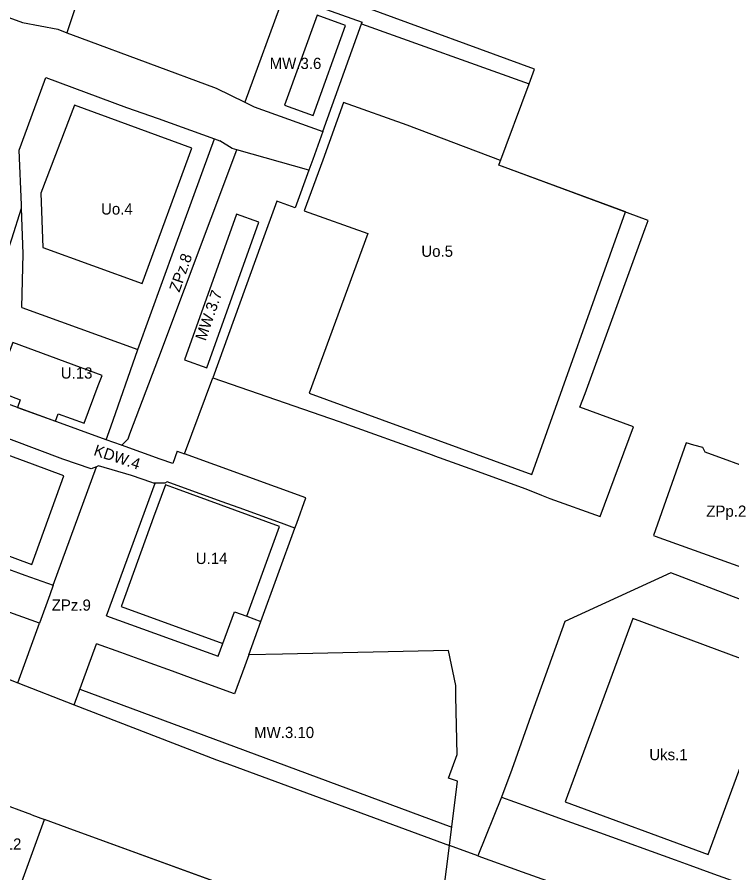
# Model space of a CAD drawing. Extents: x 7428239 to 7429836, y 5549133 to 5550853.
# Drawn here: x 7428694.2 to 7429012.7, y 5549884.9 to 5550266.4 of the extents above; entities that cross this region are included whole.
import ezdxf

# ---------------------------------------------------------------- set-up
doc = ezdxf.new("R2010")
doc.units = 0
for name, color, linetype in [('LIN_linie rozgraniczające', 7, 'Continuous'), ('LIN_nieprzekraczalna linia zabudowy', 7, 'Continuous'), ('TXT_Oznaczenia Przeznaczenia', 7, 'Continuous')]:
    doc.layers.add(name, color=color, linetype=linetype)

msp = doc.modelspace()

# ---------------------------------------------------------------- linework, layer by layer
at = {"layer": 'LIN_linie rozgraniczające'}
for p, q in [((7428813.18, 5550276.63), (7428795.72, 5550228.45)), ((7428924.77, 5550243.28), (7428850, 5550270.61)), ((7428696.63, 5550264.05), (7428712.27, 5550261)), ((7428847.7, 5550263.36), (7428922.3, 5550236.65)), ((7428922.3, 5550236.65), (7428924.77, 5550243.28)), ((7428908.84, 5550200.47), (7428922.3, 5550236.65)), ((7428830.38, 5550215.39), (7428825.9, 5550202.98)), ((7428779.91, 5550206.05), (7428782.13, 5550212.17)), ((7428764.5, 5550163.71), (7428779.91, 5550206.05)), ((7428825.9, 5550202.98), (7428824.16, 5550198.17)), ((7428824.16, 5550198.17), (7428818.13, 5550181.44)), ((7428975.37, 5550175.75), (7428908.84, 5550200.47)), ((7428809.85, 5550184.33), (7428802.95, 5550165.27)), ((7428818.13, 5550181.44), (7428809.85, 5550184.33)), ((7428974.09, 5550172.21), (7428975.37, 5550175.75)), ((7428947.38, 5550098.57), (7428974.09, 5550172.21)), ((7428747.94, 5550118.19), (7428764.5, 5550163.71)), ((7428802.95, 5550165.27), (7428781.46, 5550105.66)), ((7428696.26, 5550136.99), (7428747.94, 5550118.19)), ((7428735.94, 5550083.72), (7428747.94, 5550118.19)), ((7428768.83, 5550071.75), (7428781.46, 5550105.66)), ((7428781.46, 5550105.66), (7428837.66, 5550086.17)), ((7428944.97, 5550092.56), (7428947.38, 5550098.57)), ((7428968.89, 5550083.71), (7428944.97, 5550092.56)), ((7428733.88, 5550078.05), (7428735.94, 5550083.72)), ((7428837.66, 5550086.17), (7428879.07, 5550071.27)), ((7428954.04, 5550043.82), (7428968.89, 5550083.71)), ((7428740.76, 5550075.55), (7428733.88, 5550078.05)), ((7428765.45, 5550072.99), (7428768.83, 5550071.75)), ((7428822.87, 5550052.1), (7428768.83, 5550071.75)), ((7428879.07, 5550071.27), (7428880.14, 5550070.89)), ((7428880.14, 5550070.89), (7428895.99, 5550065.13)), ((7428710.28, 5550013.16), (7428729.5, 5550066.01)), ((7428895.99, 5550065.13), (7428920.89, 5550056.1)), ((7428734.08, 5549999.48), (7428755.65, 5550058.66)), ((7428920.89, 5550056.1), (7428927.88, 5550053.34)), ((7428927.88, 5550053.34), (7428931.57, 5550051.88)), ((7428818.77, 5550040.81), (7428822.87, 5550052.1)), ((7428931.57, 5550051.88), (7428954.04, 5550043.82)), ((7428802.85, 5549997.03), (7428817.99, 5550038.66)), ((7428817.99, 5550038.66), (7428818.76, 5550040.79)), ((7428818.76, 5550040.79), (7428818.77, 5550040.81)), ((7428694.78, 5550018.71), (7428697.6, 5550017.68)), ((7428985.48, 5550018.65), (7428938.31, 5549997.03)), ((7428697.6, 5550017.68), (7428710.28, 5550013.16)), ((7428710.28, 5550013.16), (7428708.72, 5550008.86)), ((7428708.72, 5550008.86), (7428704.16, 5549996.32)), ((7428734.08, 5549999.48), (7428783.77, 5549981.52)), ((7428788.92, 5549995.61), (7428791.01, 5550001.34)), ((7428791.01, 5550001.34), (7428796.51, 5549999.34)), ((7428796.51, 5549999.34), (7428802.85, 5549997.03)), ((7428694.46, 5549969.64), (7428704.16, 5549996.32)), ((7428785.83, 5549987.13), (7428788.92, 5549995.61)), ((7428797.45, 5549982.18), (7428802.85, 5549997.03)), ((7428719.65, 5549959.9), (7428729.56, 5549987.08)), ((7428740.34, 5549983.16), (7428729.56, 5549987.08)), ((7428783.77, 5549981.52), (7428785.83, 5549987.13)), ((7428886.38, 5549984.07), (7428812.44, 5549982.5)), ((7428889.67, 5549968.43), (7428886.38, 5549984.07)), ((7428753.5, 5549978.38), (7428740.34, 5549983.16)), ((7428797.45, 5549982.18), (7428795.65, 5549977.23)), ((7428812.44, 5549982.5), (7428797.45, 5549982.18)), ((7428763.37, 5549974.79), (7428753.5, 5549978.38)), ((7428795.65, 5549977.23), (7428791.09, 5549964.7)), ((7428680.32, 5549975.11), (7428694.46, 5549969.64)), ((7428772.67, 5549971.4), (7428763.37, 5549974.79)), ((7428694.46, 5549969.64), (7428719.65, 5549959.9)), ((7428791.09, 5549964.7), (7428772.67, 5549971.4)), ((7428889.76, 5549963.63), (7428889.67, 5549968.43)), ((7428890.24, 5549937.66), (7428889.76, 5549963.63)), ((7428719.65, 5549959.9), (7428783.02, 5549935.39)), ((7428783.02, 5549935.39), (7428789.31, 5549933.09)), ((7428886.47, 5549927.23), (7428890.24, 5549937.66)), ((7428789.31, 5549933.09), (7428886.9, 5549897.16)), ((7428890.47, 5549925.78), (7428886.47, 5549927.23)), ((7428886.9, 5549897.16), (7428890.47, 5549925.78)), ((7428700.73, 5549910.8), (7428681.94, 5549917.67)), ((7428909.98, 5549918.74), (7428899.56, 5549892.48)), ((7428909.98, 5549918.74), (7428921.55, 5549914.56)), ((7428921.55, 5549914.56), (7428937.07, 5549908.95)), ((7428694.29, 5549875.52), (7428706.34, 5549908.74)), ((7428700.73, 5549910.8), (7428706.34, 5549908.74)), ((7428716.51, 5549905.02), (7428706.34, 5549908.74)), ((7428937.07, 5549908.95), (7428953.72, 5549902.94)), ((7428861.9, 5549852.15), (7428716.51, 5549905.02)), ((7428953.72, 5549902.94), (7428987.39, 5549890.78)), ((7428880.21, 5549845.49), (7428886.9, 5549897.16)), ((7428899.56, 5549892.48), (7428886.9, 5549897.16)), ((7428899.56, 5549892.48), (7428919.18, 5549885.41)), ((7428987.39, 5549890.78), (7428993.96, 5549888.41)), ((7428919.18, 5549885.41), (7428930.47, 5549881.33)), ((7428993.96, 5549888.41), (7429002.91, 5549885.17)), ((7429002.91, 5549885.17), (7429018.14, 5549879.67))]:
    msp.add_line(p, q, dxfattribs=at)
for points in [[(7428774.34, 5550317.09), (7428726, 5550316.32), (7428726.24, 5550301.32), (7428726.42, 5550290.09), (7428716.31, 5550259.45)], [(7428665.17, 5550274.78), (7428671.25, 5550273.2), (7428696.63, 5550264.05)], [(7428813.18, 5550276.63), (7428847.92, 5550264.11)], [(7428830.38, 5550215.39), (7428847.7, 5550263.36), (7428847.92, 5550264.11)], [(7428712.27, 5550261), (7428716.31, 5550259.45), (7428721.92, 5550257.29), (7428782.94, 5550234.74), (7428795.72, 5550228.45), (7428799.81, 5550226.43), (7428830.38, 5550215.39)], [(7428696.15, 5550181.23), (7428696.09, 5550182.78), (7428695.16, 5550207.09), (7428704.73, 5550233.4), (7428706.97, 5550239.46), (7428742.92, 5550226.17), (7428757.08, 5550221.19), (7428782.13, 5550212.17), (7428784.54, 5550211.3)], [(7428824.16, 5550198.17), (7428792.12, 5550207.28), (7428790.09, 5550207.86), (7428784.54, 5550211.3)], [(7428740.76, 5550075.55), (7428741.04, 5550075.68), (7428743.67, 5550078.42), (7428744.49, 5550080.6), (7428757.32, 5550114.73), (7428792.12, 5550207.28)], [(7428682.3, 5550142.05), (7428689.53, 5550160.66), (7428691.77, 5550167.64), (7428696.15, 5550181.23)], [(7428696.26, 5550136.99), (7428696.93, 5550160.97), (7428696.15, 5550181.23)], [(7428733.88, 5550078.05), (7428694.3, 5550092.41), (7428683.29, 5550096.41)], [(7428761.01, 5550059.22), (7428759.96, 5550058.64), (7428755.65, 5550058.66), (7428754.95, 5550058.66), (7428754.25, 5550058.97), (7428745.09, 5550062.01), (7428730.44, 5550066.4), (7428729.5, 5550066.01), (7428727.12, 5550065.03), (7428714.51, 5550069.34), (7428691.75, 5550077.92), (7428686.8, 5550079.72), (7428687.28, 5550081.07), (7428686.76, 5550081.22), (7428686.13, 5550083.11), (7428685.63, 5550084.53), (7428684.79, 5550085.6), (7428679.8, 5550087.58)], [(7429032.54, 5550061.79), (7429024.72, 5550064.82), (7429024.38, 5550063.89), (7429000.78, 5550072.42), (7428999.81, 5550074.51), (7428995.7, 5550075.64), (7428992.26, 5550076.61), (7428977.71, 5550035.34), (7428978.55, 5550035.04), (7429017.02, 5550021.18)], [(7428765.45, 5550072.99), (7428763.57, 5550067.47), (7428757.91, 5550069.33), (7428740.76, 5550075.55)], [(7428817.99, 5550038.66), (7428812.05, 5550040.82), (7428793.17, 5550047.62), (7428785.15, 5550050.45), (7428761.01, 5550059.22)], [(7428628.82, 5550054.34), (7428631.27, 5550046.51), (7428633.22, 5550044.37), (7428656.8, 5550035.59), (7428668.69, 5550028.81), (7428681.6, 5550023.4), (7428694.78, 5550018.71)], [(7428704.16, 5549996.32), (7428670.08, 5550008.51), (7428633.54, 5550021.58)], [(7429025.73, 5550003.32), (7429016.5, 5550006.84), (7428985.48, 5550018.65)], [(7428938.31, 5549997.03), (7428928.29, 5549969.34), (7428923.81, 5549956.97)], [(7428923.81, 5549956.97), (7428914.57, 5549931.03), (7428909.98, 5549918.74)]]:
    msp.add_lwpolyline(points, dxfattribs=at)
at = {"layer": 'LIN_nieprzekraczalna linia zabudowy'}
for points in [[(7428840.5, 5550262.62), (7428827.86, 5550267.22), (7428813.4, 5550227.15), (7428826.08, 5550222.62), (7428840.5, 5550262.62)], [(7428923.52, 5550062.53), (7428965.31, 5550179.69), (7428908.84, 5550200.47), (7428909.61, 5550202.54), (7428867.95, 5550218.24), (7428839.65, 5550228.34), (7428830.4, 5550202.6), (7428822.14, 5550180.01), (7428850.42, 5550169.92), (7428824.34, 5550098.74), (7428923.52, 5550062.53)], [(7428772.11, 5550208.05), (7428719.74, 5550227.15), (7428704.74, 5550187.88), (7428705.71, 5550163.74)], [(7428705.71, 5550163.74), (7428749.93, 5550147.61), (7428772.11, 5550208.05)], [(7428768.84, 5550113.59), (7428778.66, 5550110.15), (7428801.91, 5550175.05), (7428792.01, 5550178.54), (7428768.84, 5550113.59)], [(7428730.33, 5550102.14), (7428732.09, 5550106.68), (7428692.23, 5550121.39), (7428690.6, 5550117.05), (7428684.24, 5550100.1), (7428695.57, 5550095.81), (7428694.3, 5550092.41), (7428711.24, 5550086.26), (7428712.45, 5550089.61), (7428724.1, 5550085.39), (7428730.33, 5550102.14)], [(7428715.06, 5550061.91), (7428701.07, 5550067.07), (7428671.04, 5550078.17), (7428666.19, 5550073.87), (7428645.67, 5550054.64), (7428641.86, 5550044.19), (7428700.72, 5550022.48), (7428715.06, 5550061.91)], [(7428796.51, 5549999.34), (7428811.1, 5550039.33), (7428765.19, 5550056.14), (7428760.24, 5550057.95), (7428755.02, 5550043.56), (7428740.65, 5550003.97), (7428740.53, 5550003.64), (7428785.83, 5549987.13)], [(7429032.2, 5549974.74), (7428968.53, 5549998.27), (7428938.39, 5549916.68), (7429002.06, 5549893.16), (7429032.2, 5549974.74)], [(7428722.16, 5549966.78), (7428887.91, 5549905.25)], [(7428861.9, 5549852.15), (7428716.51, 5549905.02), (7428706.34, 5549908.74)]]:
    msp.add_lwpolyline(points, dxfattribs=at)

# ---------------------------------------------------------------- texts
at = {"layer": 'TXT_Oznaczenia Przeznaczenia'}
for s, p in [('MW.3.6', (7428806.72, 5550243.31)), ('Uo.4', (7428731.58, 5550178.4)), ('Uo.5', (7428874.31, 5550159.57)), ('U.13', (7428713.65, 5550105.27)), ('ZPp.2', (7429001.28, 5550043.69)), ('U.14', (7428773.79, 5550022.62)), ('ZPz.9', (7428709.6, 5550001.82)), ('MW.3.10', (7428799.79, 5549945.04)), ('Uks.1', (7428975.89, 5549935.16)), ('ZPz.12', (7428674.92, 5549895.28))]:
    msp.add_text(s, height=5, dxfattribs=at).set_placement(p)
for s, rotation, p in [('ZPz.8', 70.6641, (7428766.51, 5550143.48)), ('MW.3.7', 70.9134, (7428778.15, 5550121.79)), ('KDW.4', 341.6134, (7428727.95, 5550071.28))]:
    msp.add_text(s, height=5, rotation=rotation, dxfattribs=at).set_placement(p)

doc.saveas('drawing.dxf')
